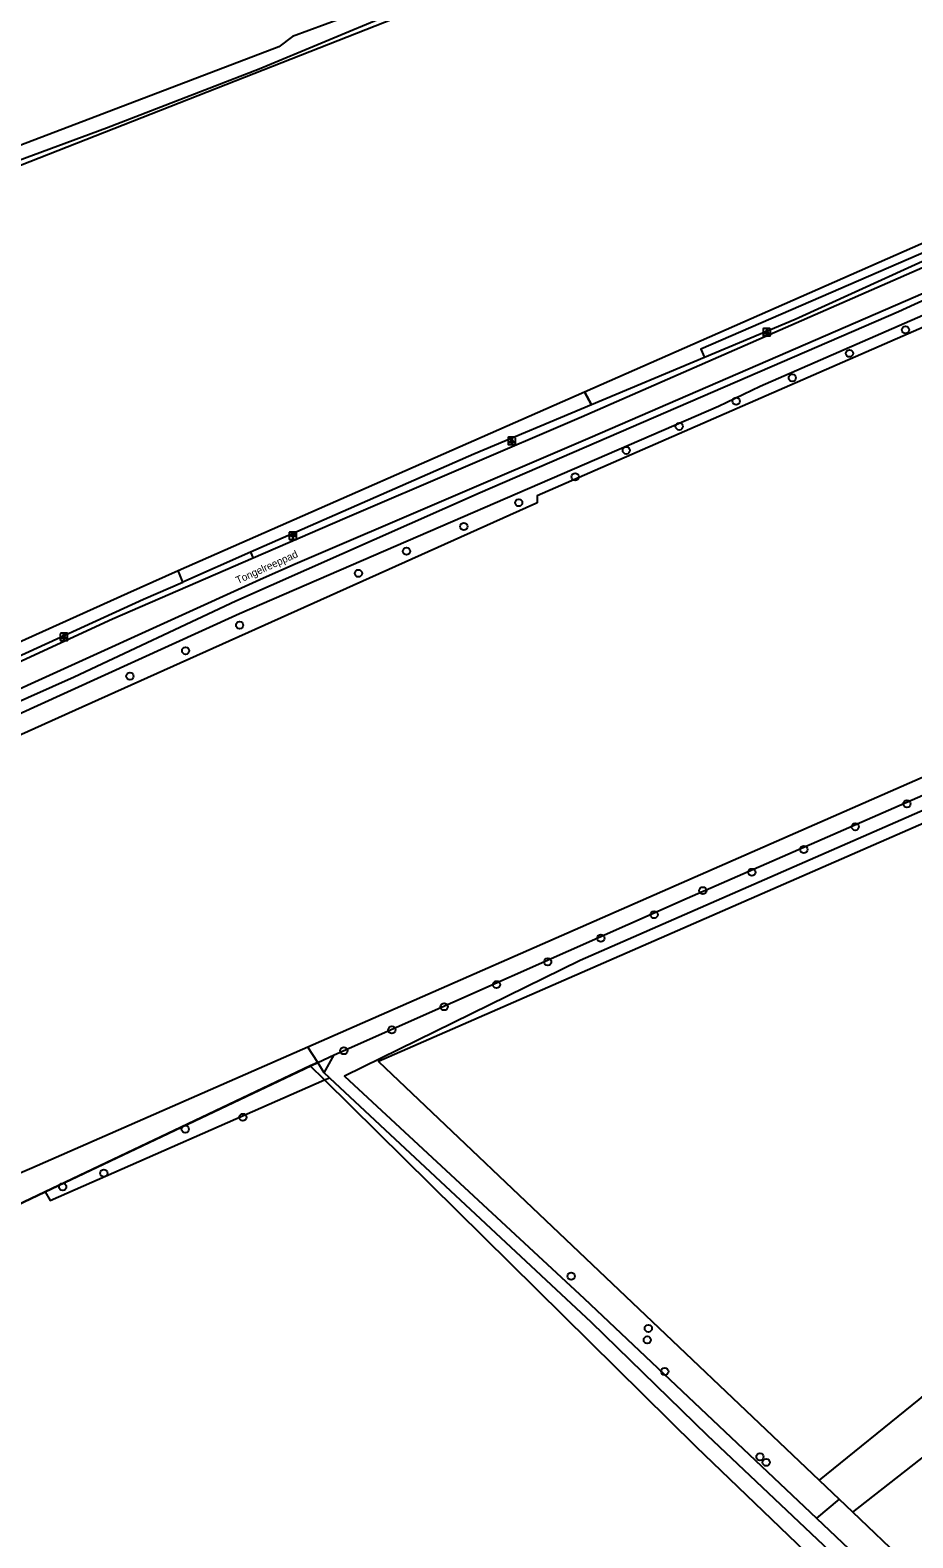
# Model space of a CAD drawing. Extents: x 160203 to 161526, y 379529 to 381797.
# Drawn here: x 161225.7 to 161344.7, y 381138.1 to 381341.3 of the extents above; entities that cross this region are included whole.
import ezdxf

# ---------------------------------------------------------------- set-up
doc = ezdxf.new("R2010")
doc.units = 0
for name, color, linetype in [('IMGEO_Boom', 7, 'Continuous'), ('IMGEO_Grasland_agrarisch', 7, 'Continuous'), ('IMGEO_Grasland_overig', 7, 'Continuous'), ('IMGEO_Groenvoorziening', 7, 'Continuous'), ('IMGEO_Hectometerpaal', 7, 'Continuous'), ('IMGEO_Hek', 7, 'Continuous'), ('IMGEO_Lichtpunt', 7, 'Continuous'), ('IMGEO_Loofbos', 7, 'Continuous'), ('IMGEO_Openbare_ruimte_label', 7, 'Continuous'), ('IMGEO_Rijbaan_lokaal_gesloten', 7, 'Continuous'), ('IMGEO_Waterloop', 7, 'Continuous')]:
    doc.layers.add(name, color=color, linetype=linetype)

msp = doc.modelspace()

# ---------------------------------------------------------------- linework, layer by layer
at = {"layer": 'IMGEO_Boom'}
for centre in [(161343.7, 381300.87), (161336.14, 381297.71), (161328.44, 381294.41), (161320.88, 381291.26), (161313.2, 381287.86), (161306.06, 381284.63), (161299.16, 381281.06), (161291.55, 381277.58), (161284.15, 381274.38), (161276.42, 381271.03), (161269.94, 381268.06), (161253.93, 381261.08), (161246.65, 381257.63), (161239.14, 381254.19), (161343.9, 381236.99), (161336.93, 381233.9), (161329.99, 381230.83), (161322.99, 381227.76), (161316.38, 381225.29), (161309.8, 381222.05), (161302.63, 381218.88), (161295.46, 381215.69), (161288.57, 381212.62), (161281.5, 381209.65), (161274.44, 381206.52), (161267.97, 381203.72), (161254.37, 381194.74), (161246.6, 381193.14), (161230.07, 381185.36), (161235.62, 381187.21), (161298.63, 381173.33), (161309.03, 381166.29), (161308.89, 381164.73), (161311.24, 381160.48), (161324.08, 381148.97), (161324.93, 381148.23)]:
    msp.add_circle(centre, 0.489, dxfattribs=at)
at = {"layer": 'IMGEO_Grasland_agrarisch'}
for points in [[(161300.42, 381292.52), (161377.22, 381326.32), (161379.59, 381328.48), (161381.46, 381331.14), (161382.56, 381334.21), (161382.85, 381337.29), (161360.06, 381376.34), (161223.13, 381322.55)], [(161245.65, 381268.42), (161300.42, 381292.52)], [(161386.66, 381258.36), (161313.5, 381226.28), (161263.14, 381204.2)], [(161388.51, 381253.22), (161360.79, 381240.78), (161272.63, 381202.28), (161332.07, 381145.82)], [(161340.38, 381132.5), (161343.66, 381134.8), (161336.59, 381141.52)]]:
    msp.add_lwpolyline(points, dxfattribs=at)
at = {"layer": 'IMGEO_Grasland_overig'}
for points in [[(161367.83, 381310.71), (161294.02, 381278.51), (161294.05, 381277.58), (161293.85, 381277.49), (161232.69, 381250), (161197.17, 381234.04)], [(161171.79, 381297.92), (161172.53, 381296.53), (161167.2, 381293.97), (161194.33, 381245.33), (161238.8, 381265.4), (161245.65, 381268.42)], [(161316.62, 381297.13), (161301.37, 381290.75)], [(161301.37, 381290.75), (161285.52, 381284.12), (161255.4, 381270.89)], [(161255.4, 381270.89), (161246.29, 381266.89)], [(161255.4, 381270.89), (161255.77, 381270.11)], [(161246.29, 381266.89), (161245.65, 381268.42)], [(161120.28, 381207.29), (161121.7, 381208.28), (161128, 381211.79), (161128.95, 381212.25), (161140.38, 381217.39), (161157.67, 381225.4), (161171.71, 381231.9), (161176.13, 381234.01), (161209.5, 381250), (161221.3, 381255.61), (161240.99, 381264.56), (161246.29, 381266.89)], [(161263.14, 381204.2), (161225.91, 381187.89), (161222.21, 381186.3), (161197.17, 381234.04)], [(161419.34, 381218.32), (161402.74, 381205.62), (161345.48, 381156.69), (161332.07, 381145.82)], [(161336.59, 381141.52), (161388.1, 381181.84), (161424.6, 381210.91)], [(161264.45, 381202.13), (161263.14, 381204.2)], [(161218.98, 381180.56), (161227.72, 381184.71)], [(161332.07, 381145.82), (161334.74, 381143.28)], [(161336.59, 381141.52), (161334.74, 381143.28)]]:
    msp.add_lwpolyline(points, dxfattribs=at)
at = {"layer": 'IMGEO_Groenvoorziening'}
for points in [[(161300.42, 381292.52), (161301.37, 381290.75)], [(161334.74, 381143.28), (161331.69, 381140.72)]]:
    msp.add_lwpolyline(points, dxfattribs=at)
at = {"layer": 'IMGEO_Hectometerpaal'}
for p, q in [((161260.61, 381273.53), (161260.61, 381272.68)), ((161260.61, 381273.53), (161260.61, 381272.68)), ((161261.53, 381273.61), (161260.69, 381273.61)), ((161261.53, 381273.61), (161260.69, 381273.61)), ((161261.61, 381272.69), (161261.61, 381273.54)), ((161261.61, 381272.69), (161261.61, 381273.54)), ((161260.7, 381272.61), (161261.54, 381272.61)), ((161260.7, 381272.61), (161261.54, 381272.61))]:
    msp.add_line(p, q, dxfattribs=at)
msp.add_lwpolyline([(161261.14, 381272.75), (161261.08, 381272.75), (161261.08, 381273.06), (161260.86, 381273.06), (161260.86, 381273.33), (161261.36, 381273.33), (161261.36, 381273.06), (161261.14, 381273.06), (161261.14, 381272.75)], dxfattribs=at)
for centre, start, end in [((161260.69, 381273.53), 92.4484, 184.2845), ((161260.69, 381273.53), 92.4484, 184.2845), ((161261.53, 381273.53), 2.4484, 94.2845), ((161261.53, 381273.53), 2.4484, 94.2845), ((161260.69, 381272.69), 182.4484, 274.2845), ((161260.69, 381272.69), 182.4484, 274.2845), ((161261.53, 381272.69), 272.4484, 4.2845), ((161261.53, 381272.69), 272.4484, 4.2845)]:
    msp.add_arc(centre, 0.0779, start, end, dxfattribs=at)
at = {"layer": 'IMGEO_Hek'}
for points in [[(161300.42, 381292.52), (161377.22, 381326.32), (161379.59, 381328.48), (161381.46, 381331.14), (161382.56, 381334.21), (161382.85, 381337.29), (161360.06, 381376.34), (161223.13, 381322.55)], [(161245.65, 381268.42), (161300.42, 381292.52)], [(161301.37, 381290.75), (161300.42, 381292.52)], [(161264.45, 381202.13), (161263.46, 381201.66)], [(161264.45, 381202.13), (161266.68, 381203.18)], [(161263.46, 381201.66), (161227.72, 381184.71)], [(161265.37, 381199.77), (161263.46, 381201.66)], [(161250.4, 381081.63), (161315.47, 381121.68), (161332.45, 381134.02), (161315.48, 381150.32), (161265.37, 381199.77)], [(161227.72, 381184.71), (161218.98, 381180.56)], [(161334.74, 381143.28), (161331.69, 381140.72)]]:
    msp.add_lwpolyline(points, dxfattribs=at)
at = {"layer": 'IMGEO_Lichtpunt'}
for p, q in [((161324.51, 381300.96), (161324.51, 381300.15)), ((161324.51, 381300.96), (161324.51, 381300.15)), ((161325.41, 381301.05), (161324.6, 381301.05)), ((161325.41, 381301.05), (161324.6, 381301.05)), ((161324.6, 381300.06), (161325.41, 381300.06)), ((161324.6, 381300.06), (161325.41, 381300.06)), ((161325.5, 381300.15), (161325.5, 381300.96)), ((161325.5, 381300.15), (161325.5, 381300.96)), ((161290.12, 381286.31), (161290.12, 381285.51)), ((161290.12, 381286.31), (161290.12, 381285.51)), ((161291.03, 381286.41), (161290.22, 381286.41)), ((161291.03, 381286.41), (161290.22, 381286.41)), ((161290.22, 381285.41), (161291.03, 381285.41)), ((161290.22, 381285.41), (161291.03, 381285.41)), ((161291.12, 381285.51), (161291.12, 381286.31)), ((161291.12, 381285.51), (161291.12, 381286.31)), ((161229.73, 381259.9), (161229.73, 381259.09)), ((161229.73, 381259.9), (161229.73, 381259.09)), ((161230.64, 381259.99), (161229.83, 381259.99)), ((161230.64, 381259.99), (161229.83, 381259.99)), ((161229.83, 381258.99), (161230.64, 381258.99)), ((161229.83, 381258.99), (161230.64, 381258.99)), ((161230.73, 381259.09), (161230.73, 381259.9)), ((161230.73, 381259.09), (161230.73, 381259.9))]:
    msp.add_line(p, q, dxfattribs=at)
for points in [[(161324.88, 381300.62), (161324.92, 381300.59), (161324.73, 381300.33), (161324.69, 381300.36), (161324.88, 381300.62)], [(161324.98, 381300.57), (161325.03, 381300.57), (161325.03, 381300.25), (161324.98, 381300.25), (161324.98, 381300.57)], [(161325.09, 381300.59), (161325.13, 381300.62), (161325.32, 381300.36), (161325.28, 381300.33), (161325.09, 381300.59)], [(161290.5, 381285.98), (161290.54, 381285.95), (161290.35, 381285.69), (161290.31, 381285.71), (161290.5, 381285.98)], [(161290.6, 381285.93), (161290.65, 381285.93), (161290.65, 381285.61), (161290.6, 381285.61), (161290.6, 381285.93)], [(161290.71, 381285.95), (161290.75, 381285.98), (161290.93, 381285.71), (161290.9, 381285.69), (161290.71, 381285.95)], [(161230.11, 381259.56), (161230.15, 381259.53), (161229.96, 381259.27), (161229.92, 381259.3), (161230.11, 381259.56)], [(161230.21, 381259.51), (161230.26, 381259.51), (161230.26, 381259.19), (161230.21, 381259.19), (161230.21, 381259.51)], [(161230.32, 381259.53), (161230.36, 381259.56), (161230.55, 381259.3), (161230.51, 381259.27), (161230.32, 381259.53)]]:
    msp.add_lwpolyline(points, dxfattribs=at)
for centre in [(161325.01, 381300.76), (161290.62, 381286.11), (161230.23, 381259.69)]:
    msp.add_circle(centre, 0.0994, dxfattribs=at)
for centre, start, end in [((161324.6, 381300.96), 90, 180), ((161324.6, 381300.96), 90, 180), ((161324.6, 381300.15), 180, 270), ((161324.6, 381300.15), 180, 270), ((161325.41, 381300.96), 0, 90), ((161325.41, 381300.96), 0, 90), ((161325.41, 381300.15), 270, 0), ((161325.41, 381300.15), 270, 360), ((161290.22, 381286.31), 90, 180), ((161290.22, 381286.31), 90, 180), ((161290.22, 381285.51), 180, 270), ((161290.22, 381285.51), 180, 270), ((161291.03, 381286.31), 0, 90), ((161291.03, 381286.31), 0, 90), ((161291.03, 381285.51), 270, 0), ((161291.03, 381285.51), 270, 360), ((161229.83, 381259.9), 90, 180), ((161229.83, 381259.9), 90, 180), ((161229.83, 381259.09), 180, 270), ((161229.83, 381259.09), 180, 270), ((161230.64, 381259.9), 0, 90), ((161230.64, 381259.9), 0, 90), ((161230.64, 381259.09), 270, 0), ((161230.64, 381259.09), 270, 360)]:
    msp.add_arc(centre, 0.0946, start, end, dxfattribs=at)
at = {"layer": 'IMGEO_Loofbos'}
for points in [[(161227.72, 381184.71), (161264.45, 381202.13)], [(161265.33, 381200.73), (161264.45, 381202.13)], [(161265.37, 381199.77), (161266.04, 381200.07)], [(161227.72, 381184.71), (161228.39, 381183.53), (161265.37, 381199.77)], [(161250.4, 381081.63), (161315.47, 381121.68), (161332.45, 381134.02), (161315.48, 381150.32), (161265.37, 381199.77)]]:
    msp.add_lwpolyline(points, dxfattribs=at)
at = {"layer": 'IMGEO_Rijbaan_lokaal_gesloten'}
for points in [[(161380.36, 381324.29), (161300.01, 381289.1), (161268.1, 381275.47), (161255.77, 381270.11)], [(161108.29, 381192.8), (161114.38, 381197.57), (161123.38, 381204.59), (161125.79, 381205.94), (161175.21, 381228.65), (161209.02, 381245.57), (161218.78, 381250), (161257.16, 381267.43), (161261.42, 381269.36), (161301.19, 381286.35), (161354.19, 381309.33), (161381.5, 381321.67)], [(161255.77, 381270.11), (161236.8, 381261.86), (161224.01, 381256), (161211.76, 381250), (161175.45, 381232.2), (161151.18, 381220.82), (161125.81, 381209.31), (161121.42, 381206.63), (161116.65, 381203.45), (161099.6, 381189.8), (161096.83, 381188), (161094.45, 381187.01), (161091.51, 381186.01)]]:
    msp.add_lwpolyline(points, dxfattribs=at)
at = {"layer": 'IMGEO_Waterloop'}
for points in [[(161222.84, 381323.27), (161236, 381328.12), (161256.58, 381336.04), (161274.27, 381343.43), (161317.03, 381359.97), (161360.4, 381377.29), (161368.59, 381365.27), (161375.96, 381351.87), (161383.45, 381338.75), (161383.7, 381336.92), (161383.67, 381335.02), (161383.36, 381333.15), (161382.76, 381331.35), (161381.9, 381329.65), (161380.79, 381328.11), (161379.45, 381326.76), (161377.81, 381325.55), (161367.25, 381320.64), (161353.54, 381314.51), (161316.1, 381298.26), (161316.62, 381297.13)], [(161365.72, 381372.42), (161369.71, 381366.2), (161384.11, 381339.39), (161384.45, 381336.97), (161384.42, 381334.95), (161384.09, 381332.97), (161383.46, 381331.05), (161382.54, 381329.26), (161381.36, 381327.63), (161379.94, 381326.2), (161377.2, 381324.16), (161372.67, 381322.04), (161352.58, 381313.11), (161328.84, 381302.29), (161316.62, 381297.13)], [(161271.8, 381344.48), (161267.66, 381342.84), (161261.05, 381340.41), (161259.23, 381339.03), (161211.51, 381320.89)], [(161195.51, 381236.36), (161194.88, 381237.74), (161206.8, 381242.94), (161222.45, 381250), (161231.6, 381254.13), (161253.42, 381264.34), (161286.37, 381278.95), (161342.74, 381303.34), (161367.3, 381314.56), (161367.99, 381314.88), (161393.64, 381326.61)], [(161196.03, 381236.58), (161207.23, 381241.35), (161226.2, 381250), (161253.93, 381262.65), (161318.49, 381290.59), (161324.1, 381293.29), (161367.27, 381312.13)], [(161265.33, 381200.73), (161266.68, 381203.18), (161314.28, 381224.26), (161373.18, 381250), (161386.95, 381256.02), (161387.72, 381254.08), (161378.24, 381250), (161353.55, 381239.38), (161299.86, 381215.86), (161268.06, 381200.27), (161300.4, 381170.33), (161331.69, 381140.72)], [(161266.04, 381200.07), (161265.33, 381200.73)], [(161266.04, 381200.07), (161301.32, 381167.14), (161316.96, 381151.91), (161335.09, 381134.8), (161338.8, 381131.3)], [(161331.69, 381140.72), (161340.38, 381132.5)]]:
    msp.add_lwpolyline(points, dxfattribs=at)

# ---------------------------------------------------------------- texts
at = {"layer": 'IMGEO_Openbare_ruimte_label'}
msp.add_text('Tongelreeppad', height=1, rotation=24.2068, dxfattribs=at).set_placement((161253.68, 381266.61))

doc.saveas('drawing.dxf')
